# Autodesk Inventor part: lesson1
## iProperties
Author: Administrator
Created: 2000-12
Part Number: lesson1
Document SubType Name: Modeling
Designer: Administrator
Control State: 0
Master: False
Checked Out: False
PropertySet Name: Design Tracking Control
Shininess: 0.0
PropertySet Name: _Private Model Information
Density: 0.0
Volumn: 0.0
Area: 0.0
PropertySet Name: Model Information
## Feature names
1. Extrusion1
